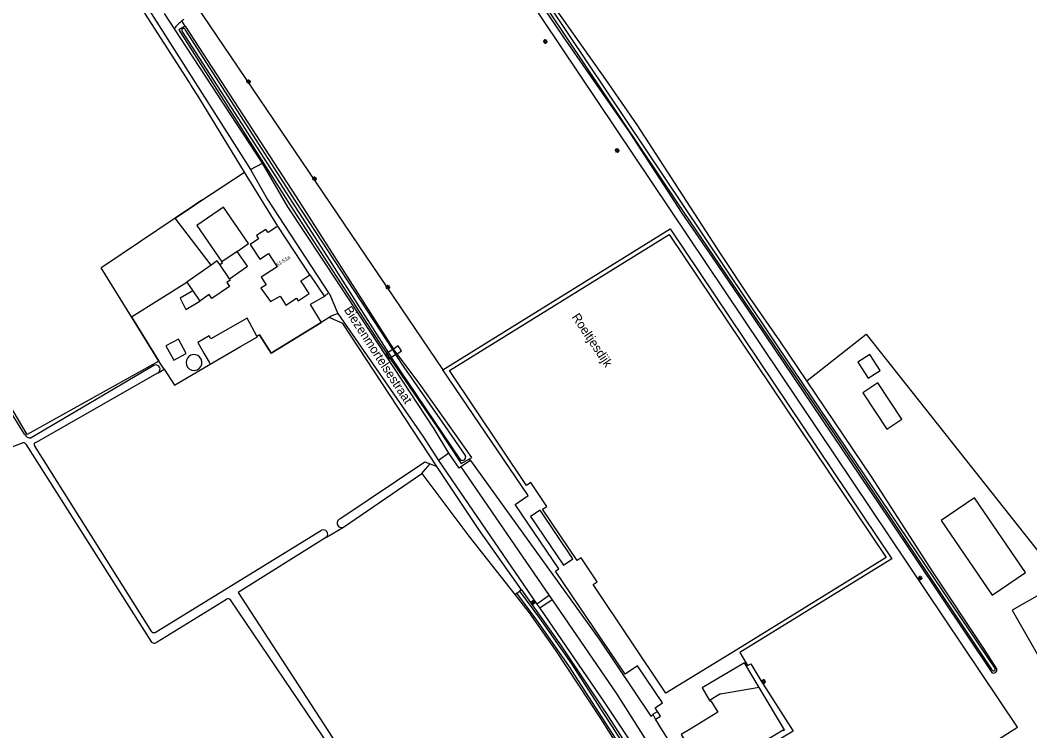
# Model space of a CAD drawing. Extents: x 140000 to 143000, y 403500 to 406000.
# Drawn here: x 140803.5 to 141083.6, y 404986.4 to 405183.6 of the extents above; entities that cross this region are included whole.
import ezdxf

# ---------------------------------------------------------------- set-up
doc = ezdxf.new("R2010")
doc.units = 0
for name, color, linetype in [('gg-afsc-erfafscheiding', 7, 'Continuous'), ('gg-afsc-hekwerk', 7, 'Continuous'), ('gg-anno-huisnummerreeks BGT', 7, 'Continuous'), ('gg-anno-openbare ruimte label', 7, 'Continuous'), ('gg-bbg-bezinkbak', 7, 'Continuous'), ('gg-bbg-bijgebouw', 7, 'Continuous'), ('gg-bbg-gedigitaliseerde bebouwing', 7, 'Continuous'), ('gg-bbg-hoofdgebouw', 7, 'Continuous'), ('gg-bbg-lage trafo', 7, 'Continuous'), ('gg-bbg-luifel en loopbrug', 7, 'Continuous'), ('gg-bbg-open loods', 7, 'Continuous'), ('gg-bbg-overig bouwwerk', 7, 'Continuous'), ('gg-bbg-tussenscheiding', 7, 'Continuous'), ('gg-knt-bronhoudergrens', 7, 'Continuous'), ('gg-knt-verharding', 7, 'Continuous'), ('gg-knt-verharding nz', 7, 'Continuous'), ('gg-kntw-bovenkant insteek waterloop', 7, 'Continuous'), ('gg-kntw-waterlijn', 7, 'Continuous'), ('gg-kwrk-kunstwerk niveau 01', 7, 'Continuous'), ('gt-grn-groengrens', 7, 'Continuous'), ('gt-grn-vlakafsluiter', 7, 'Continuous'), ('gt-grn-weggrens', 7, 'Continuous'), ('gt-symb-lichtmast', 7, 'Continuous'), ('gx-grn-maaiveld', 7, 'Continuous')]:
    doc.layers.add(name, color=color, linetype=linetype)

# ---------------------------------------------------------------- blocks, each defined once
blk = doc.blocks.new('gt0-LMAST')
at = {"layer": 'gt-symb-lichtmast'}
for p, q in [((-0.18, 0.17), (-0.45, 0.44)), ((-0.01, 0.25), (-0.01, 0.62)), ((0.17, 0.17), (0.44, 0.44)), ((-0.26, 0), (-0.63, 0)), ((-0.18, -0.18), (-0.45, -0.45)), ((-0.01, -0.25), (-0.01, -0.63)), ((0.44, -0.45), (0.17, -0.18)), ((0.24, 0), (0.62, 0))]:
    blk.add_line(p, q, dxfattribs=at)
blk.add_circle((-0.01, 0), 0.25, dxfattribs=at)

msp = doc.modelspace()

# ---------------------------------------------------------------- linework, layer by layer
at = {"layer": 'gg-afsc-erfafscheiding'}
for p, q in [((140849.27, 405181.98), (140848.32, 405183.38)), ((140874.95, 405126.41), (140865.75, 405141.42)), ((140883.86, 405112.92), (140887.94, 405106.96)), ((140834.38, 405101.29), (140841.99, 405089.01)), ((140841.74, 405085.76), (140843.45, 405086.75)), ((140928.45, 405061.45), (140928.14, 405061.9))]:
    msp.add_line(p, q, dxfattribs=at)
for points in [[(141009.3, 404942.53), (141080.23, 404987.47), (140923.11, 405221.77), (140852.23, 405187.73), (140920.77, 405086.6)], [(140856.46, 405115.61), (140846.54, 405128.68), (140851.86, 405132.25), (140853.89, 405133.61), (140865.75, 405141.42)], [(140920.77, 405086.6), (140983.86, 405125.66), (141045.29, 405034.16), (141003.19, 405008.16), (141005.26, 405004.55), (141006.17, 405005), (141009.01, 405000.4), (141017.92, 404986.29), (140992.2, 404970.87), (141009.3, 404942.53)], [(140957.99, 405033.65), (140948.44, 405047.89), (140949.6, 405048.67), (140945.14, 405055.31), (140943.98, 405054.53), (140922.58, 405086.43), (140983.54, 405124.17), (141043.74, 405034.5), (141002.64, 405009.12), (140982.65, 404996.91), (140962.45, 405027.01), (140963.61, 405027.79), (140959.15, 405034.43), (140957.99, 405033.65)], [(140919.1, 405059.77), (140892.97, 405099.39), (140889.21, 405101.1)], [(140869.18, 405095.9), (140869.88, 405096.33), (140873.09, 405091.21), (140887.01, 405099.75)], [(140843.45, 405086.75), (140842.01, 405088.97), (140841.99, 405089.01)], [(140843.45, 405086.75), (140846.29, 405082.36), (140856.24, 405088.15)], [(140980.32, 404991.82), (140979.64, 404992.82), (140981.7, 404994.22), (140974.74, 405004.48), (140971.35, 405002.18), (140951.99, 405030.74), (140952.9, 405031.36), (140940.78, 405049.24), (140944.43, 405051.7), (140920.77, 405086.6)]]:
    msp.add_lwpolyline(points, dxfattribs=at)
msp.add_arc((140854.61, 405175.18), 10.34, 123.4675, 127.4979, dxfattribs=at)
at = {"layer": 'gg-afsc-hekwerk'}
for p, q in [((140851.86, 405132.25), (140846.54, 405128.68)), ((140853.89, 405133.61), (140851.86, 405132.25)), ((140846.54, 405128.68), (140826.68, 405115.36)), ((140826.68, 405115.36), (140825.96, 405114.88)), ((140834.38, 405101.29), (140825.96, 405114.88)), ((140841.99, 405089.01), (140834.38, 405101.29)), ((140889.21, 405101.1), (140887.01, 405099.75)), ((140892.97, 405099.39), (140889.21, 405101.1)), ((140842.01, 405088.97), (140841.99, 405089.01))]:
    msp.add_line(p, q, dxfattribs=at)
msp.add_lwpolyline([(140887.01, 405099.75), (140873.09, 405091.21), (140869.88, 405096.33), (140869.18, 405095.9)], dxfattribs=at)
at = {"layer": 'gg-bbg-bezinkbak'}
for start, end in [(45.002, 179.9899), (179.9827, 45.0092)]:
    msp.add_arc((140851.72, 405088.6), 2.21, start, end, dxfattribs=at)
at = {"layer": 'gg-bbg-bijgebouw'}
for p, q in [((140856.46, 405115.61), (140849.71, 405110.95)), ((140849.71, 405110.95), (140851.4, 405108.51)), ((140851.4, 405108.51), (140853.37, 405105.66))]:
    msp.add_line(p, q, dxfattribs=at)
for points in [[(140863.73, 405119.44), (140866.87, 405121.61), (140859.88, 405131.73), (140852.49, 405126.62), (140859.47, 405116.5)], [(140861.54, 405111.82), (140866.58, 405115.3), (140863.73, 405119.44)], [(140858.88, 405115.8), (140858.19, 405116.8), (140856.46, 405115.61)], [(140858.88, 405115.8), (140859.61, 405116.31), (140859.47, 405116.5)], [(140861.54, 405111.82), (140861.79, 405111.46), (140860.8, 405110.78), (140861.54, 405109.71), (140856.71, 405106.37), (140855.96, 405107.45), (140853.37, 405105.66)], [(140869.18, 405095.9), (140866.46, 405100.87), (140856.36, 405095.19), (140855.9, 405095.99), (140852.74, 405094.15), (140854.47, 405091.18), (140855.9, 405088.72), (140856.24, 405088.15)], [(140846.09, 405089.29), (140849.52, 405091.14), (140847.38, 405095.11), (140843.95, 405093.25), (140846.09, 405089.29)], [(140856.24, 405088.15), (140864.63, 405093.05), (140869.3, 405095.69), (140869.18, 405095.9)], [(141043.9, 405070.16), (141048.09, 405072.92), (141041.48, 405082.96), (141037.29, 405080.2), (141043.9, 405070.16)], [(141107.14, 405000.71), (141107.5, 405000.91), (141114.35, 405004.82), (141137.67, 405018.13), (141127.15, 405036.56), (141117.86, 405031.26), (141113.16, 405039.5), (141078.75, 405019.86), (141093.97, 404993.19), (141101.71, 404997.61)]]:
    msp.add_lwpolyline(points, dxfattribs=at)
at = {"layer": 'gg-bbg-gedigitaliseerde bebouwing'}
msp.add_lwpolyline([(140872.27, 405124.65), (140871.68, 405125.54), (140869.07, 405123.82), (140869.66, 405122.92)], dxfattribs=at)
at = {"layer": 'gg-bbg-hoofdgebouw'}
for p, q in [((140874.95, 405126.41), (140872.27, 405124.65)), ((140883.86, 405112.92), (140874.95, 405126.41))]:
    msp.add_line(p, q, dxfattribs=at)
for points in [[(140869.66, 405122.92), (140867.33, 405121.38), (140870.01, 405117.31), (140872.37, 405118.87), (140874.44, 405115.71), (140874.78, 405115.18), (140870.36, 405112.28), (140871.74, 405110.19), (140870.29, 405109.24), (140872.91, 405105.53), (140875.64, 405106.99), (140877.24, 405104.56), (140880.13, 405106.46), (140880.62, 405105.7), (140883.68, 405107.72), (140881.34, 405111.26), (140883.61, 405112.75), (140883.86, 405112.92)], [(141008.56, 404998.42), (140997.81, 404996.59), (140997.77, 404996.66), (140994.78, 404994.87)], [(141015.31, 404986.51), (141015.56, 404986.66), (141008.56, 404998.42)], [(140994.78, 404994.87), (140994.93, 404994.62), (140995.11, 404994.73), (140997.02, 404991.55), (140989.81, 404987.18), (140986.86, 404985.41), (140993.78, 404973.85), (140996.71, 404975.61), (141015.2, 404986.69), (141015.31, 404986.51)]]:
    msp.add_lwpolyline(points, dxfattribs=at)
at = {"layer": 'gg-bbg-lage trafo'}
msp.add_line((140979.8, 404989.69), (140979.08, 404990.91), dxfattribs=at)
for points in [[(140979.08, 404990.91), (140979, 404991.04), (140980.32, 404991.82)], [(140979.8, 404989.69), (140980.26, 404989.96), (140981.12, 404990.47), (140980.32, 404991.82)]]:
    msp.add_lwpolyline(points, dxfattribs=at)
at = {"layer": 'gg-bbg-luifel en loopbrug'}
for points in [[(140851.4, 405108.51), (140847.88, 405106.46), (140849.5, 405103.36), (140853.37, 405105.66)], [(140945.1, 405045.88), (140954.23, 405032.35), (140956.85, 405034.12), (140947.72, 405047.65), (140945.1, 405045.88)], [(141008.56, 404998.42), (141004.47, 405005.3), (140992.73, 404998.31), (140994.78, 404994.87)]]:
    msp.add_lwpolyline(points, dxfattribs=at)
at = {"layer": 'gg-bbg-open loods'}
msp.add_lwpolyline([(141059.03, 405044.75), (141073.14, 405024.04), (141082.41, 405030.35), (141068.29, 405051.06), (141059.03, 405044.75)], dxfattribs=at)
at = {"layer": 'gg-bbg-overig bouwwerk'}
msp.add_lwpolyline([(141038.73, 405084.25), (141042.08, 405086.42), (141039.2, 405090.87), (141035.85, 405088.71), (141038.73, 405084.25)], dxfattribs=at)
at = {"layer": 'gg-bbg-tussenscheiding'}
for p, q in [((140863.73, 405119.44), (140859.47, 405116.5)), ((140861.54, 405111.82), (140858.88, 405115.8))]:
    msp.add_line(p, q, dxfattribs=at)
at = {"layer": 'gg-knt-bronhoudergrens'}
msp.add_line((140834.38, 405101.29), (140849.71, 405110.95), dxfattribs=at)
for points in [[(140865.75, 405141.42), (140853.13, 405162.01), (140850.88, 405165.67), (140850.48, 405166.34), (140832.88, 405193.71), (140816.3, 405217.96)], [(141021.76, 405083.49), (141038.21, 405096.5), (141089.23, 405032.03), (141183.28, 405076.31), (141198.21, 405051.7), (141241.31, 405072.38)]]:
    msp.add_lwpolyline(points, dxfattribs=at)
at = {"layer": 'gg-knt-verharding'}
for p, q in [((140846.27, 405181.22), (140843.51, 405185.44)), ((140870.69, 405143.92), (140846.27, 405181.22)), ((140867.36, 405142.18), (140870.69, 405143.92)), ((140889.04, 405107.99), (140887.94, 405106.96)), ((140889.21, 405101.1), (140887.01, 405099.75)), ((140919.52, 405061.4), (140946.86, 405021.6)), ((140928.45, 405061.45), (140925.73, 405059.64)), ((140925.73, 405059.64), (140950.24, 405023.92)), ((140950.24, 405023.92), (140946.86, 405021.6)), ((140951.05, 405022.75), (140947.66, 405020.43)), ((140950.24, 405023.92), (140951.05, 405022.75)), ((140946.86, 405021.6), (140947.66, 405020.43))]:
    msp.add_line(p, q, dxfattribs=at)
for points in [[(140696.62, 405404.11), (140745.76, 405329.12), (140774.82, 405284.61), (140792.12, 405257.91), (140813.06, 405225.13), (140823.04, 405212.19), (140836.71, 405190.58), (140867.36, 405142.18)], [(140867.36, 405142.18), (140872.09, 405133.81), (140889.04, 405107.99)], [(140922.43, 405063.5), (140918.32, 405070.17), (140891.9, 405110.45), (140877.76, 405131.82), (140870.69, 405143.92)], [(140887.94, 405106.96), (140883.97, 405104.69), (140887.01, 405099.75)], [(140891.64, 405102.17), (140915.18, 405068.19), (140919.52, 405061.4)], [(140925.73, 405059.64), (140925.27, 405059.34), (140922.43, 405063.5)], [(140928.45, 405061.45), (140964.12, 405011.85), (140978.44, 404990.48), (140979.08, 404990.91)], [(140951.05, 405022.75), (140969.01, 404996.58), (140981.55, 404976.9)], [(140947.66, 405020.43), (140965.55, 404994.4), (140976.09, 404978.51), (140978.38, 404974.88)], [(140985.87, 404979.66), (140983.53, 404983.52), (140980.5, 404988.48), (140979.8, 404989.69)]]:
    msp.add_lwpolyline(points, dxfattribs=at)
msp.add_arc((140894.31, 405092.81), 9.73, 105.9457, 121.6197, dxfattribs=at)
at = {"layer": 'gg-knt-verharding nz'}
msp.add_lwpolyline([(140889.04, 405107.99), (140889.27, 405107.64), (140891.64, 405102.17)], dxfattribs=at)
at = {"layer": 'gg-kntw-bovenkant insteek waterloop'}
for p, q in [((140804.74, 405068.71), (140737.25, 405176.68)), ((140908.08, 405091.03), (140907.11, 405092.36)), ((140905.18, 405091.1), (140906.09, 405089.78)), ((140840.58, 405087.8), (140806.53, 405067.72)), ((140839.99, 405013.91), (140807.49, 405065.6)), ((140917.23, 405060.46), (140919.1, 405059.77)), ((140893.17, 405042.92), (140914.95, 405057.81)), ((140841.27, 405013.87), (140887.12, 405042.08)), ((140841.49, 405011.14), (140860.76, 405022.96))]:
    msp.add_line(p, q, dxfattribs=at)
for points in [[(141021.76, 405083.49), (141014.25, 405094.61), (141006.04, 405106.42), (140998, 405118.55), (140974.63, 405154.55), (140966, 405167.13), (140952.71, 405185.82), (140934.15, 405213.9), (140927.14, 405224.45), (140926.37, 405225.6), (140925.03, 405227.46), (140924.4, 405228.08), (140923.66, 405228.47), (140922.77, 405228.5)], [(140843.65, 405191.98), (140843.33, 405193.24), (140878.6, 405207.95), (140896.52, 405214.11), (140917.18, 405222.04), (140919.94, 405222.74), (140920.93, 405222.99), (140923.61, 405223.67), (140924.16, 405223.48), (140924.66, 405222.98), (140925.05, 405222.6), (140938.96, 405201.43), (140954.1, 405178.96), (140972.65, 405152.38), (140987.02, 405130.04), (140995.46, 405117.81), (141004.77, 405104.25), (141044.55, 405045.1), (141073.02, 405002.63)], [(140849.27, 405181.98), (140847.55, 405180.96), (140878.42, 405132.23), (140903.1, 405094.14), (140905.18, 405091.1)], [(140849.27, 405181.98), (140880.11, 405134.56), (140907.11, 405092.36)], [(140906.09, 405089.78), (140919.15, 405070.7), (140925.85, 405060.55), (140928.14, 405061.9)], [(140928.14, 405061.9), (140928.76, 405062.26), (140914.61, 405082.19), (140908.08, 405091.03)], [(140807.82, 405066.43), (140841.68, 405085.73), (140841.71, 405085.74), (140841.74, 405085.76)], [(141074.41, 405003.64), (141070.87, 405009.25), (141056.71, 405030.53), (141039.8, 405056.77), (141021.76, 405083.49)], [(140724.13, 405035.36), (140758.73, 405049.04), (140804.16, 405066.35)], [(140805.08, 405065.99), (140805.08, 405065.95), (140839.79, 405011.26)], [(140892.18, 405045.2), (140915.74, 405061.02), (140917.23, 405060.46)], [(140942.61, 405025.56), (140930.78, 405042.3), (140919.1, 405059.77)], [(140914.95, 405057.81), (140928, 405040.44), (140940.7, 405024.24)], [(140888.51, 405040.16), (140863.97, 405024.78), (140917.53, 404942.41), (140958.66, 404879.79)], [(140942.61, 405025.56), (140953.4, 405010.29), (140966.39, 404990.89), (140974.39, 404978.38)], [(140951.99, 404883.73), (140933.63, 404913.2), (140891.63, 404978.71), (140861.84, 405022.76)], [(140940.7, 405024.24), (140944.67, 405019.17), (140951.94, 405008.85), (140964.49, 404989.86), (140972.58, 404977.1)]]:
    msp.add_lwpolyline(points, dxfattribs=at)
for centre, radius, start, end in [((140841.12, 405086.76), 1.18, 301.5662, 117.6215), ((140806.3, 405069.41), 1.71, 204.2417, 277.7853), ((140804.32, 405065.42), 0.939, 36.7837, 100.1315), ((140807.9, 405065.92), 0.524, 98.8749, 217.8287), ((140892.66, 405044.05), 1.24, 113.0818, 293.8418), ((140887.62, 405040.97), 1.21, 317.5092, 114.3143), ((140861.17, 405022.15), 0.908, 42.2016, 116.8723), ((140840.65, 405014.66), 1, 228.9205, 307.942), ((140840.68, 405011.76), 1.02, 209.5882, 322.7163), ((141073.55, 405003.36), 0.907, 234.0933, 17.57)]:
    msp.add_arc(centre, radius, start, end, dxfattribs=at)
at = {"layer": 'gg-kntw-waterlijn'}
for p, q in [((140907.76, 405090.83), (140906.87, 405092.2)), ((140905.6, 405091.38), (140906.51, 405090.04)), ((140925.53, 405061.76), (140906.51, 405090.04)), ((140940.7, 405024.24), (140941.21, 405024.59)), ((140942.61, 405025.56), (140942.04, 405025.17))]:
    msp.add_line(p, q, dxfattribs=at)
for points in [[(140841.63, 405195.37), (140842.07, 405195.17), (140842.6, 405195.24), (140863.51, 405204.19), (140879.83, 405210.59), (140906.68, 405220.56), (140919.41, 405224.97), (140921.47, 405225.73), (140921.95, 405225.8), (140922.78, 405225.81), (140923.72, 405225.7), (140924.69, 405225.38), (140925.13, 405225.17), (140925.27, 405224.99), (140950.39, 405187.49), (140992.74, 405124.29), (141018.07, 405086.51), (141073.95, 405003.62)], [(141073.12, 405003.34), (141048.28, 405040.58), (141029.27, 405069.07), (140985.91, 405132.85), (140924.72, 405224.21), (140924.17, 405224.57), (140923.38, 405224.8), (140922.6, 405224.79), (140922.07, 405224.59), (140919.68, 405223.81), (140919.11, 405223.63), (140891.38, 405213.52), (140880.77, 405209.24), (140869.07, 405205.18), (140858.51, 405200.81), (140843.59, 405193.98), (140843.2, 405193.68), (140842.95, 405193.43)], [(140848.33, 405180.58), (140864.94, 405154.97), (140888.71, 405118.03), (140904.25, 405093.39), (140905.6, 405091.38)], [(140906.87, 405092.2), (140880.01, 405133.31), (140849.3, 405181.04)], [(140927, 405062.81), (140921.46, 405070.86), (140910.07, 405087.29), (140907.76, 405090.83)], [(140941.21, 405024.59), (140946.72, 405017.13), (140955.63, 405004.43), (140974.13, 404975.77), (140991.12, 404948.96), (141005.52, 404925.98), (141008.9, 404920.85), (141023.62, 404898.52)], [(140942.04, 405025.17), (140947.55, 405017.71), (140956.48, 405004.98), (140974.97, 404976.34), (140992.16, 404949.44), (141006.48, 404926.37), (141024.08, 404898.84)]]:
    msp.add_lwpolyline(points, dxfattribs=at)
for centre, radius, start, end in [((140848.85, 405180.74), 0.546, 33.1597, 197.3159), ((140926.2, 405062.37), 0.906, 222.3207, 28.5918), ((141073.54, 405003.45), 0.442, 195.1578, 22.0813)]:
    msp.add_arc(centre, radius, start, end, dxfattribs=at)
at = {"layer": 'gg-kwrk-kunstwerk niveau 01'}
for p, q in [((140906.87, 405092.2), (140907.11, 405092.36)), ((140905.6, 405091.38), (140905.18, 405091.1)), ((140906.51, 405090.04), (140906.09, 405089.78)), ((140907.76, 405090.83), (140908.08, 405091.03))]:
    msp.add_line(p, q, dxfattribs=at)
for points in [[(140906.87, 405092.2), (140906.58, 405092.02), (140905.6, 405091.38)], [(140908.08, 405091.03), (140909.31, 405091.81), (140908.4, 405093.2), (140907.11, 405092.36)], [(140905.18, 405091.1), (140904.84, 405090.88), (140905.74, 405089.55), (140906.09, 405089.78)], [(140907.76, 405090.83), (140907.48, 405090.65), (140906.51, 405090.04)]]:
    msp.add_lwpolyline(points, dxfattribs=at)
at = {"layer": 'gt-grn-groengrens'}
msp.add_lwpolyline([(140841.99, 405089.01), (140805.46, 405068.67), (140738.47, 405181.78), (140737.27, 405184.18)], dxfattribs=at)
at = {"layer": 'gt-grn-vlakafsluiter'}
for points in [[(140914.95, 405057.81), (140915.96, 405058.98), (140917.23, 405060.46)], [(140941.21, 405024.59), (140941.54, 405024.82), (140942.04, 405025.17)]]:
    msp.add_lwpolyline(points, dxfattribs=at)
at = {"layer": 'gt-grn-weggrens'}
msp.add_line((140922.43, 405063.5), (140919.52, 405061.4), dxfattribs=at)
msp.add_arc((140854.27, 405175.7), 9.72, 127.7411, 145.386, dxfattribs=at)
at = {"layer": 'gx-grn-maaiveld'}
msp.add_line((140888.51, 405040.16), (140893.17, 405042.92), dxfattribs=at)

# ---------------------------------------------------------------- block references
at = {"layer": 'gt-symb-lichtmast'}
for p in [(140949.19, 405177.68), (140866.87, 405166.54), (140969.11, 405147.43), (140885.16, 405139.62), (140905.51, 405109.54), (141053.23, 405028.81), (140945.87, 405022.07), (141009.78, 405000.11)]:
    msp.add_blockref('gt0-LMAST', p, dxfattribs=at)

# ---------------------------------------------------------------- texts
at = {"layer": 'gg-anno-huisnummerreeks BGT'}
msp.add_text('51-51a', height=1, rotation=33.4, dxfattribs=at).set_placement((140874.96, 405115.19))
at = {"layer": 'gg-anno-openbare ruimte label'}
for s, rotation, p in [('Biezenmortelsestraat', 303.1, (140893.22, 405103.22)), ('Roeltjesdijk', 303.8, (140956.42, 405101.23))]:
    msp.add_text(s, height=2.5, rotation=rotation, dxfattribs=at).set_placement(p)

doc.saveas('drawing.dxf')
